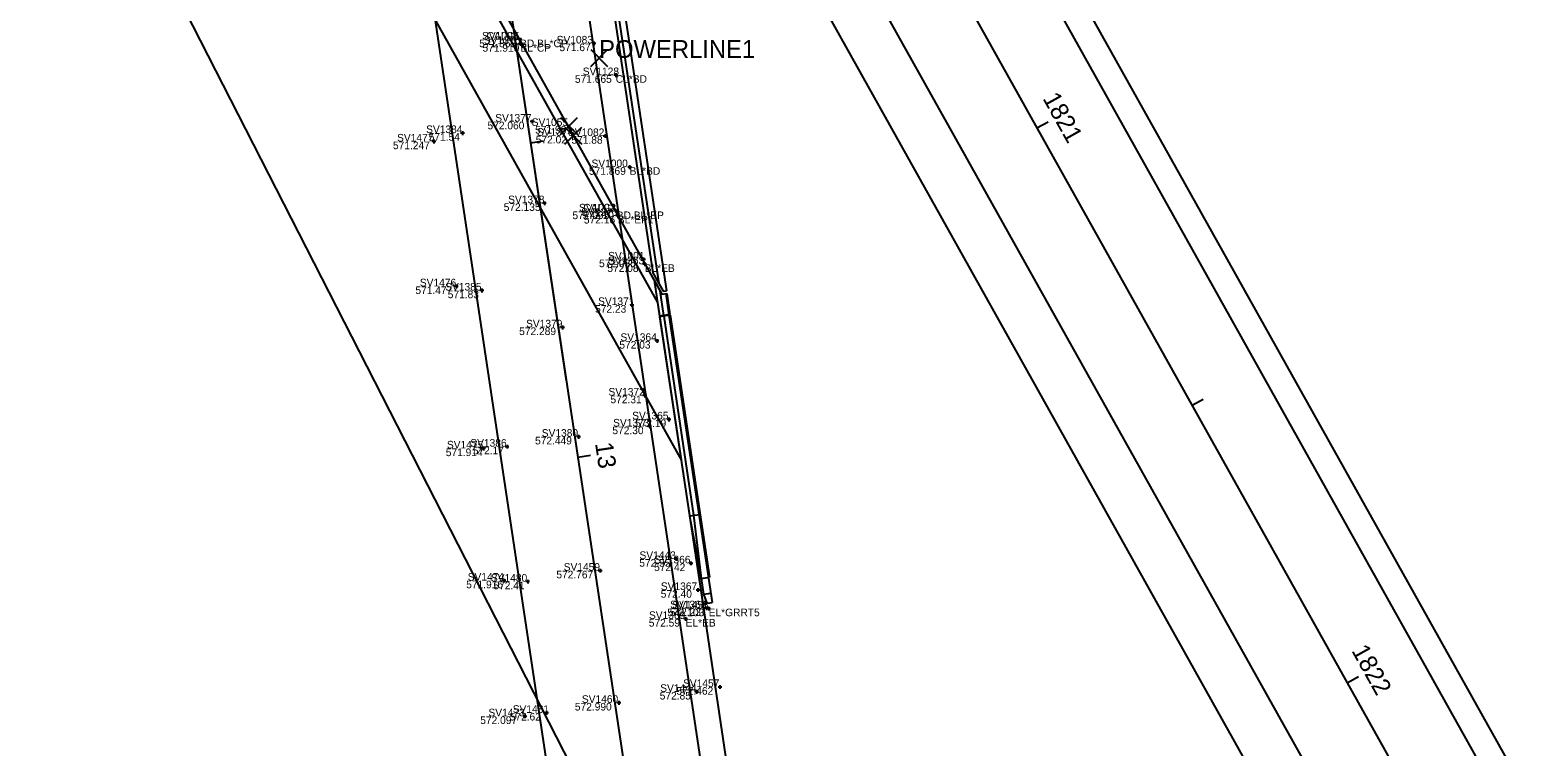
# Model space of a CAD drawing. Extents: x 6334 to 41599, y 9030 to 59113.
# Drawn here: x 21072.4 to 21309.6, y 34070.4 to 34183.1 of the extents above; entities that cross this region are included whole.
import ezdxf

# ---------------------------------------------------------------- set-up
doc = ezdxf.new("R2010")
doc.units = 0
for name, color, linetype in [('BR_X_Gen_Approach_Slab', 7, 'Continuous'), ('BR_X_Slab_Centerline', 7, 'Continuous'), ('BR_X_SV_Deck_Top', 7, 'Continuous'), ('BR_X_SV_Deck_Top_Text', 7, 'Continuous'), ('GE_P_CL_20', 7, 'Continuous'), ('GE_X_CL_20', 7, 'Continuous'), ('GK_Visualization', 7, 'Continuous'), ('PM_X_CL_Double_Solid', 7, 'Continuous'), ('PM_X_Lane_Line', 7, 'Continuous'), ('PV_X_EOP', 7, 'Continuous'), ('PV_X_Shoulder', 7, 'Continuous'), ('RW_X_Esmt_LA', 7, 'Continuous'), ('SV_X_Random_Point', 7, 'Continuous'), ('SV_X_Shot_Marker', 7, 'Continuous'), ('SV_X_Text_Comment', 7, 'Continuous'), ('SV_X_Text_Elevation', 7, 'Continuous'), ('SV_X_Text_Name', 7, 'Continuous')]:
    doc.layers.add(name, color=color, linetype=linetype)

msp = doc.modelspace()

# ---------------------------------------------------------------- linework, layer by layer
at = {"layer": 'BR_X_Gen_Approach_Slab'}
for p, q in [((21126.83, 34219.36), (21171.07, 34140.25)), ((21130.54, 34194.64), (21174.78, 34115.53)), ((21171.07, 34140.25), (21174.78, 34115.53))]:
    msp.add_line(p, q, dxfattribs=at)
at = {"layer": 'BR_X_Slab_Centerline'}
msp.add_line((21088.12, 34584.84), (21156.74, 34127.95), dxfattribs=at)
at = {"layer": 'BR_X_SV_Deck_Top'}
for p, q in [((21118.68, 34489.07), (21170.37, 34144.92)), ((21119.6, 34487.43), (21171.29, 34143.27)), ((21120.67, 34487.02), (21172.48, 34142.11)), ((21126.07, 34223.28), (21171.76, 34141.58)), ((21170.37, 34144.92), (21171.98, 34142.04)), ((21170.55, 34143.76), (21171.39, 34138.11)), ((21170.55, 34143.76), (21171.76, 34141.58)), ((21171.47, 34142.11), (21172.05, 34138.21)), ((21171.76, 34141.58), (21172.54, 34141.7)), ((21171.98, 34142.04), (21172.48, 34142.11)), ((21172.37, 34141.68), (21172.88, 34138.33)), ((21172.54, 34141.7), (21173.04, 34138.36)), ((21173.04, 34138.36), (21171.39, 34138.11)), ((21173.05, 34138.27), (21171.41, 34138.03)), ((21171.41, 34138.03), (21178.19, 34092.85)), ((21172.07, 34138.13), (21176.77, 34106.79)), ((21172.89, 34138.25), (21179.68, 34093.07)), ((21173.05, 34138.27), (21179.25, 34097.05)), ((21176.11, 34106.69), (21177.76, 34106.94)), ((21176.11, 34106.69), (21177.93, 34096.85)), ((21176.77, 34106.79), (21177.93, 34096.85)), ((21177.6, 34096.8), (21179.25, 34097.05)), ((21177.93, 34096.85), (21178.3, 34094.38)), ((21177.97, 34094.33), (21179.45, 34094.55)), ((21178.19, 34092.85), (21179.68, 34093.07)), ((21178.19, 34092.85), (21179.68, 34093.07)), ((21178.3, 34094.38), (21178.85, 34092.95))]:
    msp.add_line(p, q, dxfattribs=at)
at = {"layer": 'BR_X_SV_Deck_Top_Text'}
for p, q in [((21149.76, 34181.62), (21149.16, 34181.62)), ((21149.46, 34181.92), (21149.46, 34181.32)), ((21164.82, 34176.02), (21164.22, 34176.02)), ((21164.52, 34176.32), (21164.52, 34175.72)), ((21167, 34161.55), (21166.4, 34161.55)), ((21166.7, 34161.85), (21166.7, 34161.25)), ((21164.98, 34154.58), (21164.38, 34154.58)), ((21164.68, 34154.88), (21164.68, 34154.28)), ((21168.88, 34147.32), (21168.88, 34146.72)), ((21169.18, 34147.02), (21168.58, 34147.02))]:
    msp.add_line(p, q, dxfattribs=at)
at = {"layer": 'GE_P_CL_20'}
for p, q in [((21151.12, 34165.38), (21153.1, 34165.68)), ((21158.54, 34115.94), (21160.52, 34116.23))]:
    msp.add_line(p, q, dxfattribs=at)
at = {"layer": 'GE_X_CL_20'}
for p, q in [((21120.4, 34365.07), (21585.88, 33532.76)), ((21230.76, 34167.73), (21232.51, 34168.7)), ((21255.17, 34124.09), (21256.91, 34125.06)), ((21279.57, 34080.45), (21281.32, 34081.42))]:
    msp.add_line(p, q, dxfattribs=at)
at = {"layer": 'GK_Visualization'}
for p, q in [((21084.27, 34610.45), (21262.51, 33423.7)), ((21084.27, 34610.45), (21262.51, 33423.7)), ((21120.28, 34365.28), (21585.88, 33532.76)), ((21120.4, 34365.07), (21585.88, 33532.76)), ((21160.57, 34177.4), (21163.24, 34180.07)), ((21160.57, 34180.07), (21163.24, 34177.4))]:
    msp.add_line(p, q, dxfattribs=at)
at = {"layer": 'PM_X_CL_Double_Solid'}
msp.add_line((21084.27, 34610.45), (21262.51, 33423.7), dxfattribs=at)
at = {"layer": 'PM_X_Lane_Line'}
msp.add_line((21120.4, 34365.07), (21585.88, 33532.76), dxfattribs=at)
msp.add_line((21120.4, 34365.07), (21585.88, 33532.76), dxfattribs=at)
at = {"layer": 'PV_X_EOP'}
for p, q in [((21096.14, 34612.23), (21274.38, 33425.48)), ((21072.4, 34608.67), (21250.65, 33421.92)), ((21130.87, 34370.92), (21596.35, 33538.62)), ((21109.92, 34359.21), (21575.4, 33526.9))]:
    msp.add_line(p, q, dxfattribs=at)
at = {"layer": 'PV_X_Shoulder'}
for p, q in [((21134.36, 34372.88), (21599.84, 33540.57)), ((21102.94, 34355.3), (21568.42, 33523)), ((21178.19, 34092.85), (21278.34, 33426.08))]:
    msp.add_line(p, q, dxfattribs=at)
at = {"layer": 'RW_X_Esmt_LA'}
msp.add_line((21084.66, 34209.87), (21370.15, 33651.46), dxfattribs=at)
at = {"layer": 'SV_X_Random_Point'}
for p, q in [((21155.83, 34166.69), (21158.49, 34169.36)), ((21155.83, 34169.36), (21158.49, 34166.69)), ((21156.5, 34165.15), (21159.17, 34167.82)), ((21156.5, 34167.82), (21159.17, 34165.15))]:
    msp.add_line(p, q, dxfattribs=at)
at = {"layer": 'SV_X_Shot_Marker'}
for p, q in [((21149.76, 34181.62), (21149.16, 34181.62)), ((21149.83, 34180.92), (21149.23, 34180.92)), ((21149.46, 34181.92), (21149.46, 34181.32)), ((21149.53, 34181.22), (21149.53, 34180.62)), ((21161.39, 34181), (21160.79, 34181)), ((21161.09, 34181.3), (21161.09, 34180.7)), ((21151.66, 34168.71), (21151.06, 34168.71)), ((21151.36, 34169.01), (21151.36, 34168.41)), ((21140.72, 34166.91), (21140.12, 34166.91)), ((21140.42, 34167.21), (21140.42, 34166.61)), ((21163.15, 34166.44), (21162.55, 34166.44)), ((21162.85, 34166.74), (21162.85, 34166.14)), ((21136.21, 34165.58), (21135.61, 34165.58)), ((21135.91, 34165.88), (21135.91, 34165.28)), ((21153.59, 34155.87), (21152.99, 34155.87)), ((21153.29, 34156.17), (21153.29, 34155.57)), ((21164.98, 34154.58), (21164.38, 34154.58)), ((21164.68, 34154.88), (21164.68, 34154.28)), ((21165.15, 34153.89), (21164.55, 34153.89)), ((21164.85, 34154.19), (21164.85, 34153.59)), ((21169.37, 34146.27), (21168.77, 34146.27)), ((21169.07, 34146.57), (21169.07, 34145.97)), ((21139.74, 34142.8), (21139.14, 34142.8)), ((21139.44, 34143.1), (21139.44, 34142.5)), ((21143.75, 34142.14), (21143.15, 34142.14)), ((21143.45, 34142.44), (21143.45, 34141.84)), ((21167.06, 34140.16), (21167.06, 34139.56)), ((21167.36, 34139.86), (21166.76, 34139.86)), ((21156.44, 34136.34), (21155.84, 34136.34)), ((21156.14, 34136.64), (21156.14, 34136.04)), ((21171.31, 34134.21), (21170.71, 34134.21)), ((21171.01, 34134.51), (21171.01, 34133.91)), ((21169.09, 34125.92), (21169.09, 34125.32)), ((21169.39, 34125.62), (21168.79, 34125.62)), ((21173.18, 34121.87), (21172.58, 34121.87)), ((21172.88, 34122.17), (21172.88, 34121.57)), ((21158.98, 34119.14), (21158.38, 34119.14)), ((21158.68, 34119.44), (21158.68, 34118.84)), ((21170.15, 34120.75), (21169.55, 34120.75)), ((21169.85, 34121.05), (21169.85, 34120.45)), ((21143.99, 34117.3), (21143.39, 34117.3)), ((21143.69, 34117.6), (21143.69, 34117)), ((21147.72, 34117.58), (21147.12, 34117.58)), ((21147.42, 34117.88), (21147.42, 34117.28)), ((21174.32, 34099.91), (21173.72, 34099.91)), ((21174.02, 34100.21), (21174.02, 34099.61)), ((21162.37, 34098.07), (21161.77, 34098.07)), ((21162.07, 34098.37), (21162.07, 34097.77)), ((21176.65, 34099.22), (21176.05, 34099.22)), ((21176.35, 34099.52), (21176.35, 34098.92)), ((21147.24, 34096.51), (21146.64, 34096.51)), ((21146.94, 34096.81), (21146.94, 34096.21)), ((21150.97, 34096.35), (21150.37, 34096.35)), ((21150.67, 34096.65), (21150.67, 34096.05)), ((21177.45, 34095.33), (21177.45, 34094.73)), ((21177.75, 34095.03), (21177.15, 34095.03)), ((21175.81, 34090.48), (21175.21, 34090.48)), ((21175.51, 34090.78), (21175.51, 34090.18)), ((21179.11, 34092.16), (21178.51, 34092.16)), ((21178.81, 34092.46), (21178.81, 34091.86)), ((21179.43, 34092.11), (21178.83, 34092.11)), ((21179.13, 34092.41), (21179.13, 34091.81)), ((21177.54, 34079.01), (21176.94, 34079.01)), ((21177.24, 34079.31), (21177.24, 34078.71)), ((21181.21, 34079.77), (21180.61, 34079.77)), ((21180.91, 34080.07), (21180.91, 34079.47)), ((21165.3, 34077.28), (21164.7, 34077.28)), ((21165, 34077.58), (21165, 34076.98)), ((21150.54, 34075.16), (21149.94, 34075.16)), ((21150.24, 34075.46), (21150.24, 34074.86)), ((21153.94, 34075.71), (21153.34, 34075.71)), ((21153.64, 34076.01), (21153.64, 34075.41))]:
    msp.add_line(p, q, dxfattribs=at)

# ---------------------------------------------------------------- texts
at = {"layer": 'BR_X_SV_Deck_Top_Text'}
for s, p in [('SV1003', (21143.48, 34181.62)), ('571.863', (21143.04, 34180.42)), ('BD BL*CP', (21149.46, 34180.42)), ('571.665', (21158.09, 34174.82)), ('SV1128', (21159.32, 34176.02)), ('CL*BD', (21164.52, 34174.82)), ('571.869', (21160.3, 34160.35)), ('SV1000', (21160.7, 34161.55)), ('BL*BD', (21166.7, 34160.35)), ('572.095', (21157.7, 34153.38)), ('SV1002', (21158.73, 34154.58)), ('BD BL*EP', (21164.68, 34153.38)), ('SV1001', (21163.32, 34147.02)), ('572.035', (21161.89, 34145.82))]:
    msp.add_text(s, height=1.2, dxfattribs=at).set_placement(p)
at = {"layer": 'GE_P_CL_20'}
msp.add_text('13', height=2.8, rotation=278.5417, dxfattribs=at).set_placement((21161.25, 34118.1))
at = {"layer": 'GE_X_CL_20'}
for s, p in [('1821', (21231.6, 34172.37)), ('1822', (21280.18, 34085.5))]:
    msp.add_text(s, height=2.8, rotation=299.2167, dxfattribs=at).set_placement(p)
at = {"layer": 'GK_Visualization'}
msp.add_text('POWERLINE1', height=2.8, dxfattribs=at).set_placement((21161.9, 34178.74))
at = {"layer": 'SV_X_Text_Comment'}
for s, p in [('BL*CP', (21149.53, 34179.72)), ('BL*EP1', (21164.85, 34152.69)), ('BL*EB', (21169.07, 34145.07)), ('EL*EB', (21175.51, 34089.28)), ('EL*GRRT5', (21179.13, 34090.91))]:
    msp.add_text(s, height=1.2, dxfattribs=at).set_placement(p)
at = {"layer": 'SV_X_Text_Elevation'}
for s, p in [('571.863', (21143.04, 34180.42)), ('571.910', (21143.55, 34179.72)), ('571.67', (21155.66, 34179.8)), ('572.060', (21144.34, 34167.51)), ('571.54', (21135.09, 34165.71)), ('571.98', (21151.83, 34166.83)), ('572.02', (21151.93, 34165.29)), ('571.88', (21157.54, 34165.24)), ('571.247', (21129.47, 34164.38)), ('572.135', (21146.89, 34154.67)), ('572.10', (21159.31, 34153.38)), ('572.16', (21159.5, 34152.69)), ('572.08', (21163.19, 34145.07)), ('571.477', (21133, 34141.6)), ('571.83', (21138.09, 34140.94)), ('572.23', (21161.26, 34138.66)), ('572.289', (21149.32, 34135.14)), ('572.03', (21165.08, 34133.01)), ('572.31', (21163.68, 34124.42)), ('572.19', (21167.55, 34120.67)), ('572.449', (21151.82, 34117.94)), ('572.30', (21163.98, 34119.55)), ('571.914', (21137.78, 34116.1)), ('572.17', (21142.02, 34116.38)), ('572.55', (21168.21, 34098.71)), ('572.767', (21155.17, 34096.87)), ('572.42', (21170.55, 34098.02)), ('571.916', (21140.99, 34095.31)), ('572.41', (21145.27, 34095.15)), ('572.40', (21171.59, 34093.83)), ('572.59', (21169.71, 34089.28)), ('572.103', (21172.63, 34090.91)), ('572.23', (21173.01, 34090.96)), ('572.85', (21171.43, 34077.81)), ('572.462', (21174.05, 34078.57)), ('572.990', (21158.08, 34076.08)), ('572.097', (21143.2, 34073.96)), ('572.62', (21147.83, 34074.51))]:
    msp.add_text(s, height=1.2, dxfattribs=at).set_placement(p)
at = {"layer": 'SV_X_Text_Name'}
for s, p in [('CALC5', (21144.2, 34181.62)), ('SV1376', (21143.78, 34180.92)), ('SV1083', (21155.22, 34181)), ('SV1377', (21145.56, 34168.71)), ('SV1055', (21151.3, 34168.03)), ('SV1477', (21130.12, 34165.58)), ('SV1384', (21134.69, 34166.91)), ('SV1374', (21152.12, 34166.49)), ('SV1082', (21157.01, 34166.44)), ('SV1378', (21147.59, 34155.87)), ('SV1370', (21159.07, 34153.89)), ('CALC3', (21159.41, 34154.58)), ('SV1363', (21163.28, 34146.27)), ('SV1476', (21133.7, 34142.8)), ('SV1385', (21137.69, 34142.14)), ('SV1371', (21161.74, 34139.86)), ('SV1379', (21150.41, 34136.34)), ('SV1364', (21165.26, 34134.21)), ('SV1372', (21163.37, 34125.62)), ('SV1373', (21164.1, 34120.75)), ('SV1365', (21167.1, 34121.87)), ('SV1386', (21141.64, 34117.58)), ('SV1380', (21152.88, 34119.14)), ('SV1475', (21137.96, 34117.3)), ('SV1443', (21168.25, 34099.91)), ('SV1366', (21170.56, 34099.22)), ('SV1474', (21141.23, 34096.51)), ('SV1480', (21144.88, 34096.35)), ('SV1459', (21156.33, 34098.07)), ('SV1367', (21171.61, 34095.03)), ('SV1368', (21173.07, 34092.16)), ('SV1458', (21173.42, 34092.11)), ('SV1369', (21169.74, 34090.48)), ('SV1457', (21175.1, 34079.77)), ('SV1460', (21159.19, 34077.28)), ('SV1444', (21171.51, 34079.01)), ('SV1473', (21144.49, 34075.16)), ('SV1481', (21148.31, 34075.71))]:
    msp.add_text(s, height=1.2, dxfattribs=at).set_placement(p)

doc.saveas('drawing.dxf')
